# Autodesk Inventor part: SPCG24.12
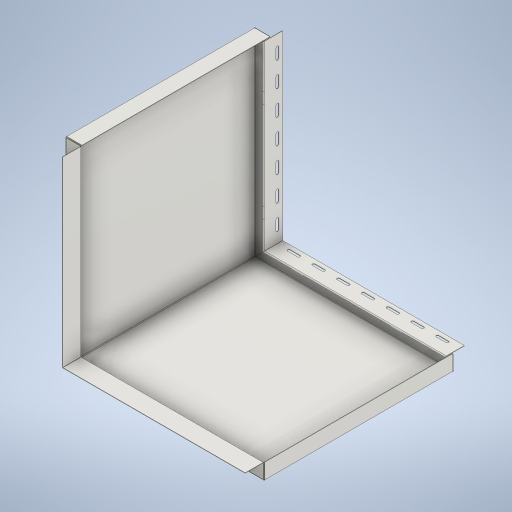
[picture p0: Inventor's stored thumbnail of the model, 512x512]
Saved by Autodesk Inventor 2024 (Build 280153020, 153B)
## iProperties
Created: 2023-02
Part Number: SPCG24.12
Material: Aluminium 6061
Document SubType Name: Modeling
Designer: Utilisateur
Density: 2.7 g/cm^3
Appearance: Acier
Major Version: 1.0
Minor Version: 7.0
Format Version: 0.0
Author: Utilisateur
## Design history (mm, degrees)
node "SPCG24_1_1:1"
node "Modification directe1"
sketch "Esquisse1"
  geometry: L1 (21.784, 7.62)-(306.783, 7.62); L2 (306.783, 7.62)-(306.783, 28.112); L3 (306.783, 28.112)-(21.784, 28.112); L4 (21.784, 28.112)-(21.784, 7.62); 2 further points
  constraints: 8 end point, 2 parallel, 1 horizontal, 1 perpendicular, 1 point on line
extrude "Extrusion1" cut sketch "Esquisse1" extent not by distance; stored distance "d3" = 0; taper "d4" = 0 deg
sketch "Esquisse2"
  geometry: L1 (-0.66, 0.66)-(-0.66, 279.881) reference; L2 (0, 0)-(-0.66, 0.66) reference; L3 (0, 279.881)-(0, 0) reference; L4 (-0.66, 279.881)-(0, 279.881) reference; L5 (-0.84, 0.481)-(-280.06, 0.481) reference; L6 (-280.06, -0.18)-(-280.06, 0.481) reference; L7 (-280.06, -0.18)-(-0.18, -0.18) reference; L8 (-0.84, 0.481)-(-0.18, -0.18) reference; 1 further point
extrude "Extrusion2" join sketch "Esquisse2" distance "d5" = 10.16; taper "d6" = 0 deg
sketch "Sketch5"
  geometry: L1 (-10.033, 23.927)-(17.78, 23.927) reference; L2 (-0.813, 21.387)-(-9.004, 21.387) reference; L3 (0, 0)-(0, 20.574) reference; L4 (-0.686, -0.803)-(-0.686, -1.468) reference; L5 (0.128, -1.133)-(0.128, -0.813) reference; L6 (0.416, -0.813)-(0.128, -0.813) reference; L7 (0.66, 0)-(0.66, 20.574) reference; L8 (-0.813, 22.047)-(-9.004, 22.047) reference; L9 (-10.033, 23.266)-(17.78, 23.266) reference; L10 (17.78, 23.927)-(17.78, 23.266) reference; L11 (-5.421, 23.927)-(-5.421, 23.266); L12 (-10.033, 23.266)-(17.78, 23.266) reference; L13 (-5.434, 22.047)-(-5.434, 21.387); L14 (-0.813, 21.387)-(-9.004, 21.387) reference; A1 r 1.397 centre (-10.033, 22.53) between (-10.033, 23.927) and (-11.43, 22.53) reference; A2 r 1.397 centre (-10.033, 22.53) between (-11.43, 22.53) and (-9.383, 21.293) reference; A3 r 0.813 centre (-9.004, 20.574) between (-9.004, 21.387) and (-9.383, 21.293) reference; A4 r 0.813 centre (-0.813, 20.574) between (0, 20.574) and (-0.813, 21.387) reference; A5 r 0.813 centre (-0.813, 0) between (-0.686, -0.803) and (0, 0) reference; A6 r 1.473 centre (-0.813, 0) between (-0.686, -1.468) and (0.128, -1.133) reference; A7 r 1.473 centre (-0.813, 0) between (0.416, -0.813) and (0.66, 0) reference; A8 r 1.473 centre (-0.813, 20.574) between (0.66, 20.574) and (-0.813, 22.047) reference; A9 r 1.473 centre (-9.004, 20.574) between (-9.004, 22.047) and (-9.69, 21.878) reference; A10 r 0.737 centre (-10.033, 22.53) between (-10.77, 22.53) and (-9.69, 21.878) reference; A11 r 0.737 centre (-10.033, 22.53) between (-10.033, 23.266) and (-10.77, 22.53) reference; 4 further points
  constraints: 4 end point, 4 point on line, 1 perpendicular, 1 vertical
extrude "Extrusion5" join sketch "Sketch5" stored distance "d27" = 25.4; taper "d28" = 0 deg
sketch "Sketch6"
  geometry: L1 (23.266, -9.803)-(23.266, -10.693) reference; L2 (23.266, -9.803)-(23.927, -9.803) reference; L3 (23.927, -10.693)-(23.927, -9.803) reference; L4 (21.375, -9.803)-(22.041, -9.803) reference; L5 (23.927, 17.12)-(23.927, -10.693) reference; L6 (21.387, -9.665)-(21.387, -1.473) reference; L7 (20.574, -0.66)-(0, -0.66) reference; L8 (-0.903, -1.473)-(-0.807, -1.573) reference; L9 (-1.098, -1.473)-(-0.903, -1.473) reference; L10 (-1.098, -1.473)-(-1.098, -0.985) reference; L11 (20.574, 0)-(0, 0) reference; L12 (22.047, -9.665)-(22.047, -1.473) reference; L13 (23.266, -10.693)-(23.266, 17.12) reference; L14 (23.927, 17.12)-(23.266, 17.12) reference; L15 (21.387, -6.112)-(22.047, -6.112); L16 (23.266, -6.112)-(23.927, -6.112); 16 further points
  constraints: 4 end point, 4 point on line, 2 perpendicular, 17 other
extrude "Extrusion6" join sketch "Sketch6" stored distance "d29" = 25.4; taper "d30" = 0 deg
sketch "Esquisse3"
  geometry: L1 (-19.479, 186.837)-(-19.479, 201.918); L2 (-17.494, 186.837)-(-17.494, 201.918); L3 (-21.463, 201.918)-(-21.463, 186.837); L4 (0, 219.778)-(-27.813, 219.778) reference; L5 (-27.813, -60.103)-(-27.813, 219.778) reference; A1 r 1.984 centre (-19.479, 186.837) between (-21.463, 186.837) and (-17.494, 186.837); A2 r 1.984 centre (-19.479, 201.918) between (-17.494, 201.918) and (-21.463, 201.918); 4 further points
  constraints: 8 end point, 6 point on circle, 4 tangent, 2 centre point, 2 parallel, 1 midpoint
  dimensions: "d8" = 19.05 distance of point (-19.479, 184.853) point (-19.479, 203.903); "d9" = 3.96875 distance between parallel lines of L3 L2; "d10" = 15.875 distance from line of L4 point (-19.479, 203.903); "d11" = 6.35 distance between parallel lines of L5 L3
extrude "Extrusion3" cut sketch "Esquisse3" extent not by distance; stored distance "d12" = 0; taper "d13" = 0 deg
pattern_linear "Réseau rectangulaire1" dims "d16" = 38.1
sketch "Esquisse4"
  geometry: L1 (201.918, -19.479)-(186.837, -19.479); L2 (201.918, -17.494)-(186.837, -17.494); L3 (186.837, -21.463)-(201.918, -21.463); L4 (219.778, 0)-(219.778, -27.813) reference; L5 (219.778, -27.813)-(-60.103, -27.813) reference; A1 r 1.984 centre (201.918, -19.479) between (201.918, -21.463) and (201.918, -17.494); A2 r 1.984 centre (186.837, -19.479) between (186.837, -17.494) and (186.837, -21.463); 4 further points
  constraints: 8 end point, 6 point on circle, 4 tangent, 2 centre point, 2 parallel, 1 midpoint
  dimensions: "d18" = 19.05 distance of point (203.903, -19.479) point (184.853, -19.479); "d19" = 3.96875 distance between parallel lines of L3 L2; "d20" = 15.875 distance from line of point (203.903, -19.479) L4; "d21" = 6.35 distance between parallel lines of L5 L3
extrude "Extrusion4" cut sketch "Esquisse4" extent not by distance; stored distance "d22" = 0; taper "d23" = 0 deg
pattern_linear "Réseau rectangulaire2" dims "d26" = 38.1
sketch "Sketch7"
  geometry: L1 (22.047, 3.835)-(0, 3.835); L2 (22.047, 3.175)-(0, 3.175); L3 (22.2, -21.565)-(22.2, 3.023); L4 (22.86, -21.565)-(22.2, -21.565); L5 (22.86, -21.565)-(22.86, 3.023); L6 (-1.473, 4.648)-(-0.813, 4.648); A1 r 0.813 centre (0, 4.648) between (-0.813, 4.648) and (0, 3.835); A2 r 0.813 centre (22.047, 3.023) between (22.86, 3.023) and (22.047, 3.835); A3 r 1.473 centre (0, 4.648) between (-0.813, 3.42) and (0, 3.175); A4 r 1.473 centre (0, 4.648) between (-1.473, 4.648) and (-1.133, 3.707); A5 r 1.473 centre (0, 4.648) between (-1.133, 3.707) and (-0.813, 3.42); A6 r 0.152 centre (22.047, 3.023) between (22.2, 3.023) and (22.047, 3.175); 4 further points
  constraints: 12 end point, 12 point on circle, 6 centre point, 1 horizontal
extrude "Extrusion7" join sketch "Sketch7" stored distance "d32" = 25.4; taper "d33" = 0 deg
sketch "Sketch8"
  geometry: L1 (22.2, -24.74)-(22.2, -0.152) reference; L2 (22.2, -0.152)-(22.2, 0.646); L3 (22.2, 3.023)-(22.2, 0.646) reference; L4 (-1.473, 1.473)-(-1.473, 4.521) reference; L5 (0, 3.175)-(22.047, 3.175) reference; L6 (-0.813, 1.473)-(-0.813, 3.42) reference; L7 (22.047, 0.66)-(0, 0.66) reference; L8 (22.047, 0)-(0, 0) reference; L9 (22.227, 0.66)-(0.18, 0.66) reference; A1 r 1.473 centre (0, 4.648) between (-0.813, 3.42) and (0, 3.175) reference; A2 r 1.482 centre (0.003, 4.657) between (-1.473, 4.521) and (0, 3.175); A3 r 1.473 centre (0, 1.473) between (-1.473, 1.473) and (-1.133, 0.532) reference; A4 r 1.473 centre (0, 1.473) between (-1.133, 0.532) and (-0.813, 0.245) reference; A5 r 1.473 centre (0, 1.473) between (-0.813, 0.245) and (0, 0) reference; A6 r 0.813 centre (0, 1.473) between (-0.813, 1.473) and (0, 0.66) reference; A7 r 0.152 centre (22.047, -0.152) between (22.2, -0.152) and (22.047, 0) reference; 2 further points
  constraints: 3 point on circle, 2 end point, 1 centre point
extrude "Extrusion8" cut sketch "Sketch8" stored distance "d34" = 25.4; taper "d35" = 0 deg
sketch "Sketch9"
  geometry: L1 (-22.225, 22.86)-(2.362, 22.86); L2 (3.988, -1.473)-(3.988, -0.813); L3 (2.515, 22.047)-(2.515, 0); L4 (-22.225, 22.86)-(-22.225, 22.2); L5 (-22.225, 22.2)-(2.362, 22.2); L6 (3.175, 22.047)-(3.175, 0); A1 r 1.473 centre (3.988, 0) between (2.515, 0) and (2.759, -0.813); A2 r 1.473 centre (3.988, 0) between (2.759, -0.813) and (3.047, -1.133); A3 r 0.813 centre (3.988, 0) between (3.175, 0) and (3.988, -0.813); A4 r 1.473 centre (3.988, 0) between (3.047, -1.133) and (3.988, -1.473); A5 r 0.813 centre (2.362, 22.047) between (3.175, 22.047) and (2.362, 22.86); A6 r 0.152 centre (2.362, 22.047) between (2.515, 22.047) and (2.362, 22.2); 4 further points
  constraints: 12 end point, 12 point on circle, 6 centre point
extrude "Extrusion9" join sketch "Sketch9" stored distance "d36" = 25.4; taper "d37" = 0 deg
sketch "Sketch10"
  geometry: L1 (-24.74, 22.2)-(-0.152, 22.2) reference; L2 (-0.152, 22.2)-(0.646, 22.2); L3 (0.66, 22.047)-(0.66, 0) reference; L4 (0, 22.047)-(0, 0) reference; L5 (1.473, -1.473)-(4.521, -1.473) reference; L6 (1.473, -0.813)-(3.42, -0.813) reference; L7 (4.648, -1.472)-(4.648, -0.809) reference; L8 (4.521, -1.473)-(4.641, -1.473) reference; L9 (4.648, -1.472)-(4.648, -1.473); L10 (4.648, -1.473)-(4.641, -1.473); A1 r 0.813 centre (-0.152, 22.047) between (0.66, 22.047) and (0.646, 22.2) reference; A2 r 0.152 centre (-0.152, 22.047) between (0, 22.047) and (-0.152, 22.2) reference; A3 r 1.473 centre (1.473, 0) between (0, 0) and (0.245, -0.813) reference; A4 r 1.473 centre (1.473, 0) between (0.245, -0.813) and (0.532, -1.133) reference; A5 r 0.813 centre (1.473, 0) between (0.66, 0) and (1.473, -0.813) reference; A6 r 1.473 centre (1.473, 0) between (0.532, -1.133) and (1.473, -1.473) reference; A7 r 1.473 centre (4.648, 0) between (3.175, 0) and (3.316, -0.629) reference; A8 r 1.472 centre (4.647, 0) between (3.175, 0) and (4.648, -1.472); 1 further point
  constraints: 6 end point, 3 point on circle, 1 centre point, 1 horizontal, 1 perpendicular
extrude "Extrusion10" cut sketch "Sketch10" stored distance "d38" = 25.4; taper "d39" = 0 deg
sketch "Sketch12"
  geometry: L1 (-1.52, -0.179)-(-0.181, -0.179) reference; L2 (-0.181, -0.179)-(-0.555, 0.195) reference; L3 (-0.375, 0.375)-(0, 0) reference; L4 (0, 1.395)-(0, 0) reference; A1 r 1.575 centre (-1.575, 1.395) between (-1.52, -0.179) and (-0.555, 0.195) reference; A2 r 1.575 centre (-1.575, 1.395) between (-0.375, 0.375) and (0, 1.395) reference
extrude "Extrusion11" cut sketch "Sketch12" extent not by distance; stored distance "d40" = 0; taper "d41" = 0 deg
sketch "Sketch14"
  geometry: L1 (-0.66, 22.047)-(-0.66, 0) reference; L2 (-2.362, 0.102)-(-0.416, 0.102) reference; L3 (-0.66, 0.102)-(-3.041, 0.102); L4 (-3.041, 0.102)-(-3.041, -1.467); L5 (0.686, -0.813)-(0.686, -1.467) reference; L6 (-3.041, -1.467)-(0.686, -1.467); A1 r 1.472 centre (0.811, 0) between (-0.416, -0.813) and (0.686, -1.467) reference; A2 r 1.473 centre (0.813, 0) between (-0.66, 0) and (-0.416, -0.813) reference; 1 further point
  constraints: 6 end point, 2 perpendicular, 2 point on line, 1 collinear
extrude "Extrusion12" cut sketch "Sketch14" stored distance "d42" = 0; taper "d43" = 0 deg
node "Solide1"
node "Boucle projetée1"
node "Boucle projetée2"
node "Projected Loop3"
node "Projected Loop4"
node "Projected Loop5"
node "Projected Loop6"
node "Projected Loop7"
feature "Echelle1"
other parameters: "d0" = 1
